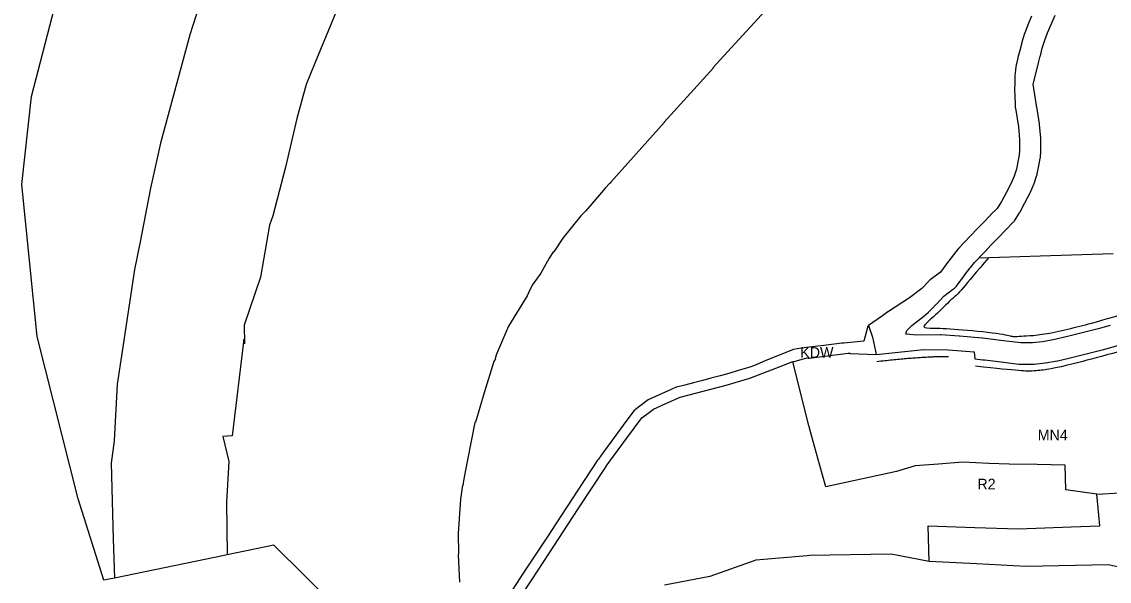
# Model space of a CAD drawing. Extents: x 7413438 to 7416393, y 5541665 to 5544118.
# Drawn here: x 7413438 to 7414051, y 5542209 to 5542525 of the extents above; entities that cross this region are included whole.
import ezdxf

# ---------------------------------------------------------------- set-up
doc = ezdxf.new("R2010")
doc.units = 0
for name, color, linetype in [('linie_rozgraniczajace', 7, 'Continuous'), ('linie_zabudowy_nieprzekraczalne', 7, 'Continuous'), ('oznaczenia_przeznaczen', 7, 'Continuous')]:
    doc.layers.add(name, color=color, linetype=linetype)

msp = doc.modelspace()

# ---------------------------------------------------------------- linework, layer by layer
at = {"layer": 'linie_rozgraniczajace'}
for p, q in [((7413547.01, 5542562.96), (7413532.36, 5542517.51)), ((7413443.1, 5542482.71), (7413457.18, 5542537.24)), ((7413863.56, 5542538.17), (7413840.24, 5542512.6)), ((7413615.78, 5542532.27), (7413602.99, 5542501.5)), ((7414005.49, 5542523.16), (7414005.4, 5542522.95)), ((7414007.54, 5542528.01), (7414005.49, 5542523.16)), ((7414016.58, 5542518.59), (7414018.59, 5542523.33)), ((7414018.59, 5542523.33), (7414020.84, 5542528.61)), ((7413532.36, 5542517.51), (7413515.88, 5542456.24)), ((7414003.62, 5542518.21), (7414002.09, 5542513.38)), ((7414003.71, 5542518.47), (7414003.62, 5542518.21)), ((7414003.73, 5542518.52), (7414003.71, 5542518.47)), ((7414005.4, 5542522.95), (7414003.73, 5542518.52)), ((7414015.01, 5542514.43), (7414016.58, 5542518.59)), ((7413840.24, 5542512.6), (7413827.7, 5542498.74)), ((7414001.99, 5542513.03), (7414000.87, 5542508.53)), ((7414002.06, 5542513.27), (7414001.99, 5542513.03)), ((7414002.09, 5542513.38), (7414002.06, 5542513.27)), ((7414013.59, 5542509.94), (7414015.01, 5542514.43)), ((7413999.84, 5542504.69), (7413999.79, 5542504.47)), ((7414000.87, 5542508.53), (7413999.84, 5542504.69)), ((7414011.47, 5542501.71), (7414012.47, 5542505.48)), ((7414012.47, 5542505.48), (7414012.49, 5542505.57)), ((7414012.49, 5542505.57), (7414013.59, 5542509.94)), ((7413602.99, 5542501.5), (7413597.99, 5542489.35)), ((7413828.06, 5542498.76), (7413800.21, 5542468.08)), ((7413827.7, 5542498.74), (7413828.06, 5542498.76)), ((7413998.93, 5542500.61), (7413998.51, 5542497.94)), ((7413999, 5542500.99), (7413998.93, 5542500.61)), ((7413999.79, 5542504.47), (7413999, 5542500.99)), ((7413999, 5542500.99), (7413999, 5542500.99)), ((7414008.49, 5542489.6), (7414010.89, 5542499.15)), ((7414010.89, 5542499.15), (7414011.47, 5542501.71)), ((7413998.17, 5542494.27), (7413998.02, 5542491.49)), ((7413998.18, 5542494.48), (7413998.17, 5542494.27)), ((7413998.46, 5542497.54), (7413998.18, 5542494.48)), ((7413998.51, 5542497.94), (7413998.46, 5542497.55)), ((7413998.46, 5542497.55), (7413998.46, 5542497.54)), ((7413998.51, 5542497.94), (7413998.51, 5542497.94)), ((7413597.99, 5542489.35), (7413592.88, 5542470.18)), ((7413998.01, 5542491.2), (7413997.98, 5542485.5)), ((7413998.02, 5542491.49), (7413998.01, 5542491.31)), ((7413998.01, 5542491.31), (7413998.01, 5542491.2)), ((7414010.3, 5542477.62), (7414008.49, 5542489.6)), ((7413437.53, 5542432.94), (7413443.1, 5542482.71)), ((7413997.98, 5542485.5), (7413997.98, 5542485.22)), ((7413997.98, 5542485.22), (7413998.02, 5542484.15)), ((7413998.02, 5542484.15), (7413998.32, 5542476.76)), ((7413998.32, 5542476.76), (7413998.35, 5542476.37)), ((7413998.35, 5542476.37), (7413998.4, 5542476.04)), ((7413998.4, 5542476.04), (7414000.12, 5542465.53)), ((7414010.63, 5542475.6), (7414010.3, 5542477.62)), ((7414012, 5542467.26), (7414010.63, 5542475.6)), ((7413592.88, 5542470.18), (7413586.41, 5542442.7)), ((7413800.33, 5542468.09), (7413770.07, 5542434.29)), ((7413800.19, 5542468.07), (7413800.33, 5542468.09)), ((7413800.21, 5542468.08), (7413800.19, 5542468.07)), ((7414000.12, 5542465.53), (7414000.79, 5542458.36)), ((7414012.04, 5542466.92), (7414012, 5542467.26)), ((7414012.05, 5542466.84), (7414012.04, 5542466.92)), ((7414012.76, 5542459.19), (7414012.05, 5542466.84)), ((7413515.88, 5542456.24), (7413510.27, 5542430.79)), ((7414000.79, 5542458.36), (7414000.78, 5542452.38)), ((7414012.78, 5542458.88), (7414012.76, 5542459.19)), ((7414012.78, 5542458.64), (7414012.78, 5542458.88)), ((7414012.78, 5542452.15), (7414012.78, 5542458.64)), ((7414000.57, 5542449.49), (7413999.87, 5542445.83)), ((7414000.78, 5542452.38), (7414000.57, 5542449.49)), ((7414012.51, 5542448.25), (7414012.77, 5542451.71)), ((7414012.77, 5542451.71), (7414012.78, 5542452)), ((7414012.78, 5542452), (7414012.78, 5542452.15)), ((7413999.87, 5542445.83), (7413999.07, 5542441.66)), ((7414010.78, 5542439.02), (7414011.65, 5542443.56)), ((7414011.65, 5542443.56), (7414011.66, 5542443.57)), ((7414011.66, 5542443.57), (7414012.42, 5542447.57)), ((7414012.42, 5542447.57), (7414012.45, 5542447.77)), ((7414012.45, 5542447.77), (7414012.5, 5542448.16)), ((7414012.5, 5542448.16), (7414012.51, 5542448.25)), ((7413586.41, 5542442.7), (7413579.18, 5542415.28)), ((7413997.74, 5542437.6), (7413996.01, 5542433.62)), ((7413999.07, 5542441.66), (7413997.74, 5542437.6)), ((7414009.06, 5542433.6), (7414010.59, 5542438.3)), ((7414010.59, 5542438.3), (7414010.64, 5542438.46)), ((7414010.64, 5542438.46), (7414010.74, 5542438.84)), ((7414010.74, 5542438.84), (7414010.78, 5542439.02)), ((7413446.14, 5542347.12), (7413437.53, 5542432.94)), ((7413767.03, 5542430.99), (7413755.9, 5542418.09)), ((7413769.38, 5542433.53), (7413767.03, 5542430.99)), ((7413769.54, 5542433.55), (7413769.38, 5542433.53)), ((7413770.07, 5542434.29), (7413769.54, 5542433.55)), ((7413996.01, 5542433.62), (7413993.17, 5542428.27)), ((7414006.92, 5542428.62), (7414008.86, 5542433.07)), ((7414008.86, 5542433.07), (7414008.99, 5542433.39)), ((7414008.99, 5542433.39), (7414009.06, 5542433.6)), ((7413510.27, 5542430.79), (7413504.29, 5542400.67)), ((7413993.16, 5542428.25), (7413990.58, 5542423.34)), ((7413993.17, 5542428.27), (7413993.16, 5542428.25)), ((7414003.77, 5542422.65), (7414006.72, 5542428.2)), ((7414006.72, 5542428.2), (7414006.73, 5542428.23)), ((7414006.73, 5542428.23), (7414006.9, 5542428.58)), ((7414006.9, 5542428.58), (7414006.92, 5542428.62)), ((7413988.07, 5542419.46), (7413984.43, 5542415.76)), ((7413990.58, 5542423.34), (7413988.07, 5542419.46)), ((7414001.07, 5542417.52), (7414003.77, 5542422.65)), ((7413579.18, 5542415.28), (7413577.31, 5542410.08)), ((7413753.13, 5542415.29), (7413743.02, 5542402.74)), ((7413753.15, 5542415.27), (7413753.13, 5542415.29)), ((7413755.9, 5542418.09), (7413753.15, 5542415.27)), ((7413984.36, 5542415.69), (7413980.21, 5542411.33)), ((7413984.43, 5542415.76), (7413984.36, 5542415.69)), ((7413997.81, 5542412.43), (7414000.8, 5542417.05)), ((7414000.8, 5542417.05), (7414000.88, 5542417.18)), ((7414000.88, 5542417.18), (7414001.07, 5542417.52)), ((7413577.31, 5542410.08), (7413572.24, 5542380.58)), ((7413976.54, 5542407.63), (7413973.53, 5542404.36)), ((7413976.69, 5542407.79), (7413976.54, 5542407.63)), ((7413980.21, 5542411.33), (7413976.69, 5542407.79)), ((7413988.86, 5542403.01), (7413993.02, 5542407.38)), ((7413993.02, 5542407.38), (7413997.05, 5542411.48)), ((7413997.05, 5542411.48), (7413997.18, 5542411.62)), ((7413997.18, 5542411.62), (7413997.44, 5542411.92)), ((7413997.44, 5542411.92), (7413997.68, 5542412.23)), ((7413997.68, 5542412.23), (7413997.81, 5542412.43)), ((7413504.29, 5542400.67), (7413501.13, 5542384.99)), ((7413743.02, 5542402.74), (7413737.96, 5542394.92)), ((7413973.53, 5542404.36), (7413969.51, 5542400.14)), ((7413985.29, 5542399.41), (7413988.77, 5542402.92)), ((7413988.77, 5542402.92), (7413988.86, 5542403.01)), ((7413737.77, 5542395.12), (7413735.27, 5542391.3)), ((7413737.96, 5542394.92), (7413737.77, 5542395.12)), ((7413966.12, 5542396.58), (7413963.48, 5542393.3)), ((7413966.13, 5542396.59), (7413966.12, 5542396.58)), ((7413966.39, 5542396.89), (7413966.13, 5542396.59)), ((7413966.47, 5542396.98), (7413966.39, 5542396.89)), ((7413969.51, 5542400.14), (7413966.47, 5542396.98)), ((7413978.19, 5542391.85), (7413982.25, 5542396.12)), ((7413982.25, 5542396.12), (7413982.32, 5542396.19)), ((7413982.32, 5542396.19), (7413985.29, 5542399.41)), ((7413735.27, 5542391.3), (7413730.58, 5542382.9)), ((7413960.69, 5542389.69), (7413956.06, 5542383.46)), ((7413960.76, 5542389.79), (7413960.69, 5542389.69)), ((7413963.4, 5542393.21), (7413960.76, 5542389.79)), ((7413963.48, 5542393.3), (7413963.4, 5542393.21)), ((7413973.21, 5542386.26), (7413975.3, 5542388.85)), ((7413975.3, 5542388.85), (7413977.88, 5542391.53)), ((7413977.88, 5542391.53), (7414012.45, 5542392.63)), ((7413977.88, 5542391.53), (7413978.17, 5542391.83)), ((7413978.17, 5542391.83), (7413978.19, 5542391.85)), ((7414012.45, 5542392.63), (7414053.52, 5542393.94)), ((7413501.13, 5542384.99), (7413494.28, 5542338.72)), ((7413730.58, 5542382.9), (7413725.57, 5542376.08)), ((7413956.06, 5542383.46), (7413950.32, 5542379.16)), ((7413969.54, 5542381.48), (7413970.29, 5542382.5)), ((7413970.29, 5542382.5), (7413972.86, 5542385.82)), ((7413972.86, 5542385.82), (7413973.21, 5542386.26)), ((7413572.24, 5542380.58), (7413563.1, 5542353.46)), ((7413725.57, 5542376.08), (7413723.61, 5542371.74)), ((7413949.51, 5542378.42), (7413945.57, 5542374.15)), ((7413949.79, 5542378.7), (7413949.51, 5542378.42)), ((7413950.08, 5542378.97), (7413949.79, 5542378.7)), ((7413950.32, 5542379.16), (7413950.08, 5542378.97)), ((7413965.18, 5542375.61), (7413969.54, 5542381.48)), ((7413722.89, 5542370.15), (7413712.2, 5542353.03)), ((7413723.5, 5542371.8), (7413722.89, 5542370.15)), ((7413723.53, 5542371.79), (7413723.5, 5542371.8)), ((7413723.61, 5542371.74), (7413723.53, 5542371.79)), ((7413945.57, 5542374.15), (7413938.54, 5542368.88)), ((7413954.02, 5542365.61), (7413957.96, 5542369.89)), ((7413957.96, 5542369.89), (7413962.93, 5542373.61)), ((7413962.93, 5542373.61), (7413963.96, 5542374.38)), ((7413963.96, 5542374.38), (7413964.2, 5542374.58)), ((7413964.2, 5542374.58), (7413964.5, 5542374.84)), ((7413964.5, 5542374.84), (7413964.77, 5542375.12)), ((7413964.77, 5542375.12), (7413965.03, 5542375.41)), ((7413965.03, 5542375.41), (7413965.18, 5542375.61)), ((7413938.54, 5542368.88), (7413926.76, 5542361.2)), ((7413949.36, 5542360.78), (7413952.47, 5542364.11)), ((7413952.47, 5542364.11), (7413952.74, 5542364.53)), ((7413952.74, 5542364.53), (7413953.21, 5542364.88)), ((7413953.21, 5542364.88), (7413953.45, 5542365.07)), ((7413953.45, 5542365.07), (7413953.75, 5542365.33)), ((7413953.75, 5542365.33), (7413954.02, 5542365.61)), ((7413923.35, 5542358.82), (7413915.52, 5542353.32)), ((7413926.47, 5542361), (7413923.35, 5542358.82)), ((7413926.5, 5542361.03), (7413926.47, 5542361)), ((7413926.76, 5542361.2), (7413926.5, 5542361.03)), ((7413939.9, 5542353.39), (7413946.63, 5542358.65)), ((7413946.63, 5542358.65), (7413949.36, 5542360.78)), ((7413563.1, 5542353.46), (7413563.23, 5542343.01)), ((7413712.2, 5542353.03), (7413705.43, 5542337.13)), ((7413915.11, 5542353.04), (7413912.93, 5542344.56)), ((7413915.52, 5542353.32), (7413915.11, 5542353.04)), ((7413915.52, 5542353.32), (7413917.68, 5542346.8)), ((7413937.16, 5542350.46), (7413939.9, 5542353.39)), ((7414045.09, 5542351.41), (7414027.9, 5542347.16)), ((7414051.95, 5542353.4), (7414045.09, 5542351.41)), ((7413469.29, 5542255.54), (7413446.14, 5542347.12)), ((7413562.94, 5542345.64), (7413556.34, 5542291.07)), ((7413563.23, 5542343.01), (7413562.94, 5542345.64)), ((7413917.68, 5542346.8), (7413919.51, 5542338.81)), ((7413936.49, 5542348.39), (7413937.16, 5542350.46)), ((7413936.7, 5542348.37), (7413936.49, 5542348.39)), ((7413942.74, 5542347.86), (7413936.7, 5542348.37)), ((7413955.93, 5542348.07), (7413942.74, 5542347.86)), ((7413956.18, 5542348.06), (7413955.93, 5542348.07)), ((7413956.41, 5542348.05), (7413956.18, 5542348.06)), ((7413966.63, 5542347.41), (7413956.41, 5542348.05)), ((7413966.79, 5542347.4), (7413966.63, 5542347.41)), ((7413966.81, 5542347.4), (7413966.79, 5542347.4)), ((7413979.57, 5542346.19), (7413966.81, 5542347.4)), ((7413979.76, 5542346.17), (7413979.57, 5542346.19)), ((7413993.16, 5542344.47), (7413979.76, 5542346.17)), ((7414019.75, 5542345.16), (7414013.71, 5542344.17)), ((7414027.9, 5542347.16), (7414019.75, 5542345.16)), ((7414048.31, 5542339.85), (7414070.22, 5542346.19)), ((7413873.21, 5542339.76), (7413867.92, 5542337.63)), ((7413875.17, 5542340.12), (7413873.21, 5542339.76)), ((7413877.74, 5542340.46), (7413875.17, 5542340.12)), ((7413882.03, 5542341.04), (7413877.74, 5542340.46)), ((7413890.34, 5542342.13), (7413882.03, 5542341.04)), ((7413900.51, 5542343.29), (7413890.34, 5542342.13)), ((7413901.55, 5542343.41), (7413900.51, 5542343.29)), ((7413912.93, 5542344.56), (7413901.55, 5542343.41)), ((7413901.55, 5542343.41), (7413901.55, 5542343.41)), ((7413919.85, 5542336.9), (7413946.81, 5542339.78)), ((7413946.81, 5542339.78), (7413960.37, 5542339.57)), ((7413960.37, 5542339.57), (7413975.07, 5542338.49)), ((7414001.42, 5542343.54), (7413993.16, 5542344.47)), ((7414007.98, 5542343.57), (7414001.42, 5542343.54)), ((7414013.71, 5542344.17), (7414007.98, 5542343.57)), ((7414030.78, 5542335.51), (7414048.08, 5542339.79)), ((7414048.08, 5542339.79), (7414048.31, 5542339.85)), ((7413494.28, 5542338.72), (7413491.43, 5542320.21)), ((7413704.01, 5542333.1), (7413698.64, 5542315.41)), ((7413704.92, 5542334.5), (7413704.01, 5542333.1)), ((7413705.43, 5542337.13), (7413704.7, 5542334.73)), ((7413704.7, 5542334.73), (7413704.92, 5542334.5)), ((7413857.19, 5542333.32), (7413852.44, 5542331.41)), ((7413867.92, 5542337.63), (7413857.19, 5542333.32)), ((7413865.7, 5542330.27), (7413872.77, 5542333.11)), ((7413872.77, 5542333.11), (7413872.88, 5542332.8)), ((7413872.84, 5542332.74), (7413872.88, 5542332.8)), ((7413881.84, 5542296.82), (7413872.84, 5542332.74)), ((7413872.88, 5542332.8), (7413873.61, 5542333.01)), ((7413873.61, 5542333.01), (7413880.69, 5542335.04)), ((7413880.69, 5542335.04), (7413881.38, 5542334.9)), ((7413881.38, 5542334.9), (7413881.96, 5542334.98)), ((7413881.96, 5542334.98), (7413903.95, 5542337.64)), ((7413903.95, 5542337.64), (7413904.52, 5542337.69)), ((7413904.52, 5542337.69), (7413904.64, 5542337.7)), ((7413904.64, 5542337.7), (7413904.95, 5542337.73)), ((7413904.95, 5542337.73), (7413905.11, 5542337.58)), ((7413905.11, 5542337.58), (7413919.85, 5542336.9)), ((7413919.51, 5542338.81), (7413919.85, 5542336.9)), ((7413975.07, 5542338.49), (7413975.52, 5542334.52)), ((7413975.52, 5542334.52), (7413975.53, 5542334.51)), ((7413975.53, 5542334.51), (7413980.11, 5542334.01)), ((7413980.11, 5542334.01), (7413980.1, 5542334.03)), ((7413980.1, 5542334.03), (7413981.07, 5542333.91)), ((7413981.07, 5542333.91), (7413991.69, 5542332.56)), ((7414015.48, 5542332.3), (7414021.92, 5542333.35)), ((7414021.92, 5542333.35), (7414021.97, 5542333.36)), ((7414021.97, 5542333.36), (7414022.36, 5542333.44)), ((7414022.36, 5542333.44), (7414022.38, 5542333.45)), ((7414022.38, 5542333.45), (7414030.77, 5542335.51)), ((7414030.77, 5542335.51), (7414030.78, 5542335.51)), ((7413842.15, 5542327.97), (7413835.41, 5542325.93)), ((7413849.12, 5542330.08), (7413842.15, 5542327.97)), ((7413848.57, 5542323.64), (7413865.7, 5542330.27)), ((7413852.44, 5542331.41), (7413849.12, 5542330.08)), ((7413991.69, 5542332.56), (7413991.78, 5542332.55)), ((7413991.78, 5542332.55), (7414000.42, 5542331.58)), ((7414000.42, 5542331.58), (7414000.55, 5542331.57)), ((7414000.55, 5542331.57), (7414000.94, 5542331.54)), ((7414000.94, 5542331.54), (7414001.12, 5542331.54)), ((7414001.12, 5542331.54), (7414008.33, 5542331.57)), ((7414008.33, 5542331.57), (7414008.55, 5542331.57)), ((7414008.55, 5542331.57), (7414008.93, 5542331.6)), ((7414008.93, 5542331.6), (7414015.13, 5542332.25)), ((7414015.13, 5542332.25), (7414015.14, 5542332.25)), ((7414015.14, 5542332.25), (7414015.48, 5542332.3)), ((7413816.62, 5542320.98), (7413811.74, 5542319.71)), ((7413822.03, 5542322.38), (7413816.62, 5542320.98)), ((7413826.41, 5542323.52), (7413822.03, 5542322.38)), ((7413831.83, 5542324.92), (7413826.41, 5542323.52)), ((7413835.41, 5542325.93), (7413831.83, 5542324.92)), ((7413835.2, 5542319.6), (7413848.57, 5542323.64)), ((7413491.43, 5542320.21), (7413489.69, 5542288.27)), ((7413698.64, 5542315.41), (7413693.66, 5542298.78)), ((7413802.02, 5542316.23), (7413797.32, 5542314.15)), ((7413806.99, 5542318.44), (7413802.02, 5542316.23)), ((7413809.48, 5542319.13), (7413806.99, 5542318.44)), ((7413811.74, 5542319.71), (7413809.48, 5542319.13)), ((7413814.23, 5542314.16), (7413835.2, 5542319.6)), ((7413791.19, 5542311.41), (7413786.43, 5542307.81)), ((7413793.27, 5542312.35), (7413791.19, 5542311.41)), ((7413797.32, 5542314.15), (7413793.27, 5542312.35)), ((7413794.17, 5542306.18), (7413801.16, 5542309.29)), ((7413801.16, 5542309.29), (7413809.2, 5542312.86)), ((7413809.2, 5542312.86), (7413814.23, 5542314.16)), ((7413783.1, 5542305.13), (7413777.02, 5542297.13)), ((7413786.43, 5542307.81), (7413783.1, 5542305.13)), ((7413787.6, 5542301.15), (7413791.86, 5542304.41)), ((7413791.86, 5542304.41), (7413794.17, 5542306.18)), ((7413693.23, 5542298.51), (7413689.06, 5542277.42)), ((7413693.6, 5542298.84), (7413693.23, 5542298.51)), ((7413693.66, 5542298.78), (7413693.6, 5542298.84)), ((7413777.02, 5542297.13), (7413770.42, 5542288.07)), ((7413778.91, 5542289.54), (7413787.6, 5542301.15)), ((7413883.24, 5542291.22), (7413881.84, 5542296.82)), ((7413556.34, 5542291.07), (7413551.05, 5542290.67)), ((7413551.05, 5542290.67), (7413554.46, 5542276.58)), ((7413887.99, 5542274.38), (7413883.24, 5542291.22)), ((7413489.69, 5542288.27), (7413487.93, 5542275.59)), ((7413770.42, 5542288.07), (7413765.79, 5542281.72)), ((7413767.5, 5542273.87), (7413778.91, 5542289.54)), ((7413763.01, 5542277.9), (7413762.57, 5542277.3)), ((7413765.79, 5542281.72), (7413763.01, 5542277.9)), ((7413487.93, 5542275.59), (7413489.09, 5542232.96)), ((7413554.46, 5542276.58), (7413553.12, 5542253.58)), ((7413689.06, 5542277.42), (7413687.11, 5542266.75)), ((7413762.57, 5542277.3), (7413751.07, 5542259.8)), ((7413751.68, 5542249.81), (7413767.46, 5542273.82)), ((7413767.46, 5542273.82), (7413767.5, 5542273.87)), ((7413891.44, 5542262.18), (7413887.99, 5542274.38)), ((7413941.75, 5542274.17), (7413931.35, 5542270.93)), ((7413954.91, 5542275.1), (7413941.75, 5542274.17)), ((7413968.82, 5542276.17), (7413954.91, 5542275.1)), ((7413983.49, 5542275.5), (7413968.82, 5542276.17)), ((7413994.97, 5542274.98), (7413983.49, 5542275.5)), ((7414010.7, 5542274.84), (7413994.97, 5542274.98)), ((7414026.51, 5542274.5), (7414010.7, 5542274.84)), ((7414026.51, 5542274.46), (7414026.51, 5542274.5)), ((7414026.82, 5542260.58), (7414026.51, 5542274.46)), ((7413687.11, 5542266.75), (7413686.45, 5542263.03)), ((7413931.35, 5542270.93), (7413891.44, 5542262.18)), ((7413686.25, 5542263.24), (7413685.19, 5542255.28)), ((7413686.45, 5542263.03), (7413686.25, 5542263.24)), ((7413751.07, 5542259.8), (7413739.35, 5542241.97)), ((7414044.41, 5542258.1), (7414026.82, 5542260.58)), ((7413483.92, 5542209.49), (7413469.29, 5542255.54)), ((7413553.12, 5542253.58), (7413553.39, 5542223.86)), ((7413685.19, 5542255.28), (7413683.86, 5542235.9)), ((7414045.44, 5542246.35), (7414044.41, 5542258.1)), ((7414044.41, 5542258.1), (7414044.42, 5542258.1)), ((7414044.42, 5542258.1), (7414044.41, 5542258.1)), ((7414044.42, 5542258.1), (7414057.78, 5542258.79)), ((7413734.97, 5542224.39), (7413751.68, 5542249.81)), ((7413739.35, 5542241.97), (7413734.03, 5542233.88)), ((7414046.01, 5542240.32), (7414045.44, 5542246.35)), ((7413683.86, 5542235.9), (7413684.05, 5542224.52)), ((7413949.64, 5542220.07), (7413949.13, 5542240.19)), ((7413949.13, 5542240.19), (7413975.48, 5542239.36)), ((7413975.48, 5542239.36), (7414000.2, 5542238.58)), ((7414000.2, 5542238.58), (7414029.9, 5542239.71)), ((7414029.9, 5542239.71), (7414046.01, 5542240.32)), ((7413489.09, 5542232.96), (7413489.83, 5542210.71)), ((7413579.77, 5542229.31), (7413553.39, 5542223.86)), ((7413661.48, 5542148.73), (7413579.77, 5542229.31)), ((7413734.03, 5542233.88), (7413720.99, 5542214.05)), ((7413552.71, 5542223.72), (7413489.83, 5542210.71)), ((7413553.39, 5542223.86), (7413552.71, 5542223.72)), ((7413683.95, 5542223.84), (7413683.89, 5542223.9)), ((7413683.89, 5542223.9), (7413684.71, 5542208.4)), ((7413684.05, 5542224.52), (7413683.95, 5542223.84)), ((7413725.36, 5542209.76), (7413734.97, 5542224.39)), ((7413880.82, 5542223.39), (7413851.81, 5542220.88)), ((7413882.12, 5542223.51), (7413880.82, 5542223.39)), ((7413928.33, 5542224.22), (7413882.12, 5542223.51)), ((7413949.64, 5542220.07), (7413928.33, 5542224.22)), ((7413851.81, 5542220.88), (7413825.92, 5542211.63)), ((7413976.52, 5542218.73), (7413949.64, 5542220.07)), ((7414004.26, 5542217.34), (7413976.52, 5542218.73)), ((7414051.03, 5542218.3), (7414004.26, 5542217.34)), ((7414078.37, 5542212.1), (7414051.03, 5542218.3)), ((7413489.83, 5542210.71), (7413483.92, 5542209.49)), ((7413720.99, 5542214.05), (7413712.28, 5542200.78)), ((7413825.92, 5542211.63), (7413800.37, 5542206.67)), ((7413717.59, 5542197.95), (7413725.36, 5542209.76))]:
    msp.add_line(p, q, dxfattribs=at)
at = {"layer": 'linie_zabudowy_nieprzekraczalne'}
for points, degree in [([(7413983.42, 5542391.67), (7413975.93, 5542383.31), (7413968.07, 5542372.87), (7413961.61, 5542367.64), (7413951.75, 5542357.6), (7413944.41, 5542351.85), (7413951.42, 5542351.96), (7413966.81, 5542351.37), (7413993.57, 5542348.41), (7413996.71, 5542346.81), (7414001.57, 5542347.51), (7414007.7, 5542347.53), (7414018.88, 5542349.04), (7414033.73, 5542352.7), (7414045.1, 5542355.56), (7414072.97, 5542364), (7414109.91, 5542374.85), (7414122.61, 5542377.91), (7414155.85, 5542385.56), (7414184.53, 5542392.37), (7414212.91, 5542399.7), (7414233.97, 5542404.86), (7414254.75, 5542409.33), (7414272.68, 5542415.25), (7414275.42, 5542416.19), (7414284.57, 5542416.89), (7414290.06, 5542416.76), (7414296.11, 5542415.63), (7414309.03, 5542412.62), (7414312.52, 5542411.12)], 3), ([(7414224.75, 5542381.75), (7414144.14, 5542362.04), (7414083.57, 5542345.67), (7414026.49, 5542330.32), (7414015.48, 5542328.23), (7414008.78, 5542327.55), (7414000.84, 5542327.51), (7413975.89, 5542330.4)], 3), ([(7413960.63, 5542335.72), (7413947.24, 5542335.89), (7413920.2, 5542332.89)], 2)]:
    msp.add_open_spline(points, degree=degree, dxfattribs=at)

# ---------------------------------------------------------------- texts
at = {"layer": 'oznaczenia_przeznaczen'}
for s, p in [('KDW', (7413876.99, 5542335.12)), ('MN4', (7414011.02, 5542288.51)), ('R2', (7413976.95, 5542260.81))]:
    msp.add_text(s, height=6, dxfattribs=at).set_placement(p)

doc.saveas('drawing.dxf')
